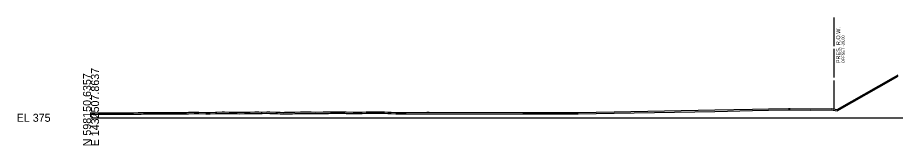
# Model space of a CAD drawing. Extents: x -26 to 2203, y -10 to 12201.
# Drawn here: x -25.7 to 281.5, y 1990.3 to 2035.1 of the extents above; entities that cross this region are included whole.
import ezdxf

# ---------------------------------------------------------------- set-up
doc = ezdxf.new("R2010")
doc.units = 0
for name, color, linetype in [('DESIGN - SHEET - Light Grid', 7, 'Continuous'), ('SURVEY - GROUND - Bottom of Topsoil Layer', 7, 'Continuous'), ('SURVEY - GROUND - Top of Ground', 7, 'Continuous'), ('SURVEY - PROPERTY - ROW Lines', 7, 'Continuous'), ('SURVEY - PROPERTY - ROW Lines Text', 7, 'Continuous')]:
    doc.layers.add(name, color=color, linetype=linetype)

msp = doc.modelspace()

# ---------------------------------------------------------------- linework, layer by layer
at = {"layer": 'DESIGN - SHEET - Light Grid'}
msp.add_line((0, 2000), (300, 2000), dxfattribs=at)
at = {"layer": 'SURVEY - GROUND - Bottom of Topsoil Layer'}
for p, q in [((261.07, 2002.43), (280.8, 2013.6)), ((280.8, 2013.6), (282.41, 2014.53)), ((237.01, 2002.63), (244.02, 2002.74)), ((244.02, 2002.74), (244.6, 2002.77)), ((244.6, 2002.77), (251.59, 2002.61)), ((251.59, 2002.61), (258.93, 2002.79)), ((258.93, 2002.79), (261.07, 2002.43)), ((0, 2001.21), (0.79, 2001.2)), ((0.79, 2001.2), (1.61, 2001.18)), ((1.61, 2001.18), (2.75, 2001.21)), ((2.75, 2001.21), (4.26, 2001.23)), ((4.26, 2001.23), (7.42, 2001.25)), ((7.42, 2001.25), (10.16, 2001.25)), ((10.16, 2001.25), (12.22, 2001.25)), ((12.22, 2001.25), (13.51, 2001.26)), ((13.51, 2001.26), (14.87, 2001.27)), ((14.87, 2001.27), (16.47, 2001.31)), ((16.47, 2001.31), (17.52, 2001.32)), ((17.52, 2001.32), (18.43, 2001.33)), ((18.43, 2001.33), (20.39, 2001.33)), ((20.39, 2001.33), (21.04, 2001.34)), ((21.04, 2001.34), (22.35, 2001.35)), ((22.35, 2001.35), (22.82, 2001.35)), ((22.82, 2001.35), (23.79, 2001.37)), ((23.79, 2001.37), (25.47, 2001.39)), ((25.47, 2001.39), (26.27, 2001.38)), ((26.27, 2001.38), (28.23, 2001.4)), ((28.23, 2001.4), (28.56, 2001.39)), ((28.56, 2001.39), (30.19, 2001.36)), ((30.19, 2001.36), (30.77, 2001.36)), ((30.77, 2001.36), (31.97, 2001.38)), ((31.97, 2001.38), (33.42, 2001.4)), ((33.42, 2001.4), (34.12, 2001.43)), ((34.12, 2001.43), (36.07, 2001.45)), ((36.07, 2001.45), (37.68, 2001.45)), ((37.68, 2001.45), (40.15, 2001.39)), ((40.15, 2001.39), (41.71, 2001.39)), ((41.71, 2001.39), (43.62, 2001.48)), ((43.62, 2001.48), (44.02, 2001.49)), ((44.02, 2001.49), (45.88, 2001.54)), ((45.88, 2001.54), (46.67, 2001.54)), ((46.67, 2001.54), (48.34, 2001.51)), ((48.34, 2001.51), (49.32, 2001.49)), ((49.32, 2001.49), (49.8, 2001.48)), ((49.8, 2001.48), (51.14, 2001.45)), ((51.14, 2001.45), (51.97, 2001.44)), ((51.97, 2001.44), (53.72, 2001.47)), ((53.72, 2001.47), (54.63, 2001.51)), ((54.63, 2001.51), (55.68, 2001.52)), ((55.68, 2001.52), (57.28, 2001.53)), ((57.28, 2001.53), (58.67, 2001.53)), ((58.67, 2001.53), (59.6, 2001.51)), ((59.6, 2001.51), (59.93, 2001.51)), ((59.93, 2001.51), (61.56, 2001.56)), ((61.56, 2001.56), (62.58, 2001.54)), ((62.58, 2001.54), (64.7, 2001.48)), ((64.7, 2001.48), (65.23, 2001.47)), ((65.23, 2001.47), (66.2, 2001.43)), ((66.2, 2001.43), (67.44, 2001.4)), ((67.44, 2001.4), (67.88, 2001.41)), ((67.88, 2001.41), (68.79, 2001.43)), ((68.79, 2001.43), (70.53, 2001.44)), ((70.53, 2001.44), (71.36, 2001.47)), ((71.36, 2001.47), (73.32, 2001.54)), ((73.32, 2001.54), (73.72, 2001.54)), ((73.72, 2001.54), (75.83, 2001.53)), ((75.83, 2001.53), (76.98, 2001.53)), ((76.98, 2001.53), (78.48, 2001.52)), ((78.48, 2001.52), (81.25, 2001.54)), ((81.25, 2001.54), (83.12, 2001.55)), ((83.12, 2001.55), (83.78, 2001.56)), ((83.78, 2001.56), (85.16, 2001.59)), ((85.16, 2001.59), (86.43, 2001.61)), ((86.43, 2001.61), (87.04, 2001.61)), ((87.04, 2001.61), (88.78, 2001.56)), ((88.78, 2001.56), (89.25, 2001.54)), ((89.25, 2001.54), (91.73, 2001.51)), ((91.73, 2001.51), (92.92, 2001.5)), ((92.92, 2001.5), (94.39, 2001.51)), ((94.39, 2001.51), (94.88, 2001.51)), ((94.88, 2001.51), (96.3, 2001.56)), ((96.3, 2001.56), (97.04, 2001.57)), ((97.04, 2001.57), (98.78, 2001.57)), ((98.78, 2001.57), (101.53, 2001.59)), ((101.53, 2001.59), (102.34, 2001.58)), ((102.34, 2001.58), (102.73, 2001.56)), ((102.73, 2001.56), (103.83, 2001.52)), ((103.83, 2001.52), (104.69, 2001.48)), ((104.69, 2001.48), (104.99, 2001.47)), ((104.99, 2001.47), (106.65, 2001.4)), ((106.65, 2001.4), (107.64, 2001.36)), ((107.64, 2001.36), (108.61, 2001.36)), ((108.61, 2001.36), (110.29, 2001.35)), ((110.29, 2001.35), (117.52, 2001.41)), ((117.52, 2001.41), (118.34, 2001.42)), ((118.34, 2001.42), (151.15, 2001.39)), ((151.15, 2001.39), (170.43, 2001.33)), ((170.43, 2001.33), (183.03, 2001.62)), ((183.03, 2001.62), (218.3, 2002.25)), ((218.3, 2002.25), (231.46, 2002.56)), ((231.46, 2002.56), (237.01, 2002.63))]:
    msp.add_line(p, q, dxfattribs=at)
at = {"layer": 'SURVEY - GROUND - Top of Ground'}
for p, q in [((280.8, 2014.1), (282.41, 2015.03)), ((261.07, 2002.93), (280.8, 2014.1)), ((183.03, 2002.12), (218.3, 2002.75)), ((218.3, 2002.75), (231.46, 2003.06)), ((231.46, 2003.06), (237.01, 2003.13)), ((237.01, 2003.13), (244.02, 2003.24)), ((244.02, 2003.24), (244.6, 2003.27)), ((244.6, 2003.27), (251.59, 2003.11)), ((251.59, 2003.11), (258.93, 2003.29)), ((258.93, 2003.29), (261.07, 2002.93)), ((0, 2001.71), (0.79, 2001.7)), ((0.79, 2001.7), (1.61, 2001.68)), ((1.61, 2001.68), (2.75, 2001.71)), ((2.75, 2001.71), (4.26, 2001.73)), ((4.26, 2001.73), (7.42, 2001.75)), ((7.42, 2001.75), (10.16, 2001.75)), ((10.16, 2001.75), (12.22, 2001.75)), ((12.22, 2001.75), (13.51, 2001.76)), ((13.51, 2001.76), (14.87, 2001.77)), ((14.87, 2001.77), (16.47, 2001.81)), ((16.47, 2001.81), (17.52, 2001.82)), ((17.52, 2001.82), (18.43, 2001.83)), ((18.43, 2001.83), (20.39, 2001.83)), ((20.39, 2001.83), (21.04, 2001.84)), ((21.04, 2001.84), (22.35, 2001.85)), ((22.35, 2001.85), (22.82, 2001.85)), ((22.82, 2001.85), (23.79, 2001.87)), ((23.79, 2001.87), (25.47, 2001.89)), ((25.47, 2001.89), (26.27, 2001.88)), ((26.27, 2001.88), (28.23, 2001.9)), ((28.23, 2001.9), (28.56, 2001.89)), ((28.56, 2001.89), (30.19, 2001.86)), ((30.19, 2001.86), (30.77, 2001.86)), ((30.77, 2001.86), (31.97, 2001.88)), ((31.97, 2001.88), (33.42, 2001.9)), ((33.42, 2001.9), (34.12, 2001.93)), ((34.12, 2001.93), (36.07, 2001.95)), ((36.07, 2001.95), (37.68, 2001.95)), ((37.68, 2001.95), (40.15, 2001.89)), ((40.15, 2001.89), (41.71, 2001.89)), ((41.71, 2001.89), (43.62, 2001.98)), ((43.62, 2001.98), (44.02, 2001.99)), ((44.02, 2001.99), (45.88, 2002.04)), ((45.88, 2002.04), (46.67, 2002.04)), ((46.67, 2002.04), (48.34, 2002.01)), ((48.34, 2002.01), (49.32, 2001.99)), ((49.32, 2001.99), (49.8, 2001.98)), ((49.8, 2001.98), (51.14, 2001.95)), ((51.14, 2001.95), (51.97, 2001.94)), ((51.97, 2001.94), (53.72, 2001.97)), ((53.72, 2001.97), (54.63, 2002.01)), ((54.63, 2002.01), (55.68, 2002.02)), ((55.68, 2002.02), (57.28, 2002.03)), ((57.28, 2002.03), (58.67, 2002.03)), ((58.67, 2002.03), (59.6, 2002.01)), ((59.6, 2002.01), (59.93, 2002.01)), ((59.93, 2002.01), (61.56, 2002.06)), ((61.56, 2002.06), (62.58, 2002.04)), ((62.58, 2002.04), (64.7, 2001.98)), ((64.7, 2001.98), (65.23, 2001.97)), ((65.23, 2001.97), (66.2, 2001.93)), ((66.2, 2001.93), (67.44, 2001.9)), ((67.44, 2001.9), (67.88, 2001.91)), ((67.88, 2001.91), (68.79, 2001.93)), ((68.79, 2001.93), (70.53, 2001.94)), ((70.53, 2001.94), (71.36, 2001.97)), ((71.36, 2001.97), (73.32, 2002.04)), ((73.32, 2002.04), (73.72, 2002.04)), ((73.72, 2002.04), (75.83, 2002.03)), ((75.83, 2002.03), (76.98, 2002.03)), ((76.98, 2002.03), (78.48, 2002.02)), ((78.48, 2002.02), (81.25, 2002.04)), ((81.25, 2002.04), (83.12, 2002.05)), ((83.12, 2002.05), (83.78, 2002.06)), ((83.78, 2002.06), (85.16, 2002.09)), ((85.16, 2002.09), (86.43, 2002.11)), ((86.43, 2002.11), (87.04, 2002.11)), ((87.04, 2002.11), (88.78, 2002.06)), ((88.78, 2002.06), (89.25, 2002.04)), ((89.25, 2002.04), (91.73, 2002.01)), ((91.73, 2002.01), (92.92, 2002)), ((92.92, 2002), (94.39, 2002.01)), ((94.39, 2002.01), (94.88, 2002.01)), ((94.88, 2002.01), (96.3, 2002.06)), ((96.3, 2002.06), (97.04, 2002.07)), ((97.04, 2002.07), (98.78, 2002.07)), ((98.78, 2002.07), (101.53, 2002.09)), ((101.53, 2002.09), (102.34, 2002.08)), ((102.34, 2002.08), (102.73, 2002.06)), ((102.73, 2002.06), (103.83, 2002.02)), ((103.83, 2002.02), (104.69, 2001.98)), ((104.69, 2001.98), (104.99, 2001.97)), ((104.99, 2001.97), (106.65, 2001.9)), ((106.65, 2001.9), (107.64, 2001.86)), ((107.64, 2001.86), (108.61, 2001.86)), ((108.61, 2001.86), (110.29, 2001.85)), ((110.29, 2001.85), (117.52, 2001.91)), ((117.52, 2001.91), (118.34, 2001.92)), ((118.34, 2001.92), (151.15, 2001.89)), ((151.15, 2001.89), (170.43, 2001.83)), ((170.43, 2001.83), (183.03, 2002.12))]:
    msp.add_line(p, q, dxfattribs=at)
at = {"layer": 'SURVEY - PROPERTY - ROW Lines'}
for p, q in [((260, 2025.11), (260, 2035.11)), ((260, 2014.11), (260, 2024.11)), ((260, 2003.11), (260, 2013.11))]:
    msp.add_line(p, q, dxfattribs=at)

# ---------------------------------------------------------------- texts
at = {"layer": 'DESIGN - SHEET - Light Grid'}
for s, p in [('N 598150.6357', (0, 1990)), ('E 1432507.8637', (2.8, 1990))]:
    msp.add_text(s, height=2.8, rotation=90, dxfattribs=at).set_placement(p)
msp.add_text('EL 375', height=2.8, dxfattribs=at).set_placement((-26, 1998.6))
at = {"layer": 'SURVEY - PROPERTY - ROW Lines Text'}
for s, height, p in [('PRES. R.O.W.', 1.4, (262.15, 2019.11)), ('OFFSET -39.00', 1, (263.65, 2019.11))]:
    msp.add_text(s, height=height, rotation=90, dxfattribs=at).set_placement(p)

doc.saveas('drawing.dxf')
